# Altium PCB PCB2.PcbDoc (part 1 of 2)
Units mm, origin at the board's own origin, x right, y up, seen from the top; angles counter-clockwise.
Board outline 153.67 x 113.03 mm, 4 copper layers (Top Layer, Mid Layer 1, Mid Layer 2, Bottom Layer), stack 1.57 mm thick; 123 components, 293 nets, 917 pads, 135 vias.
Unrouted connection lines stored in the file: 517.
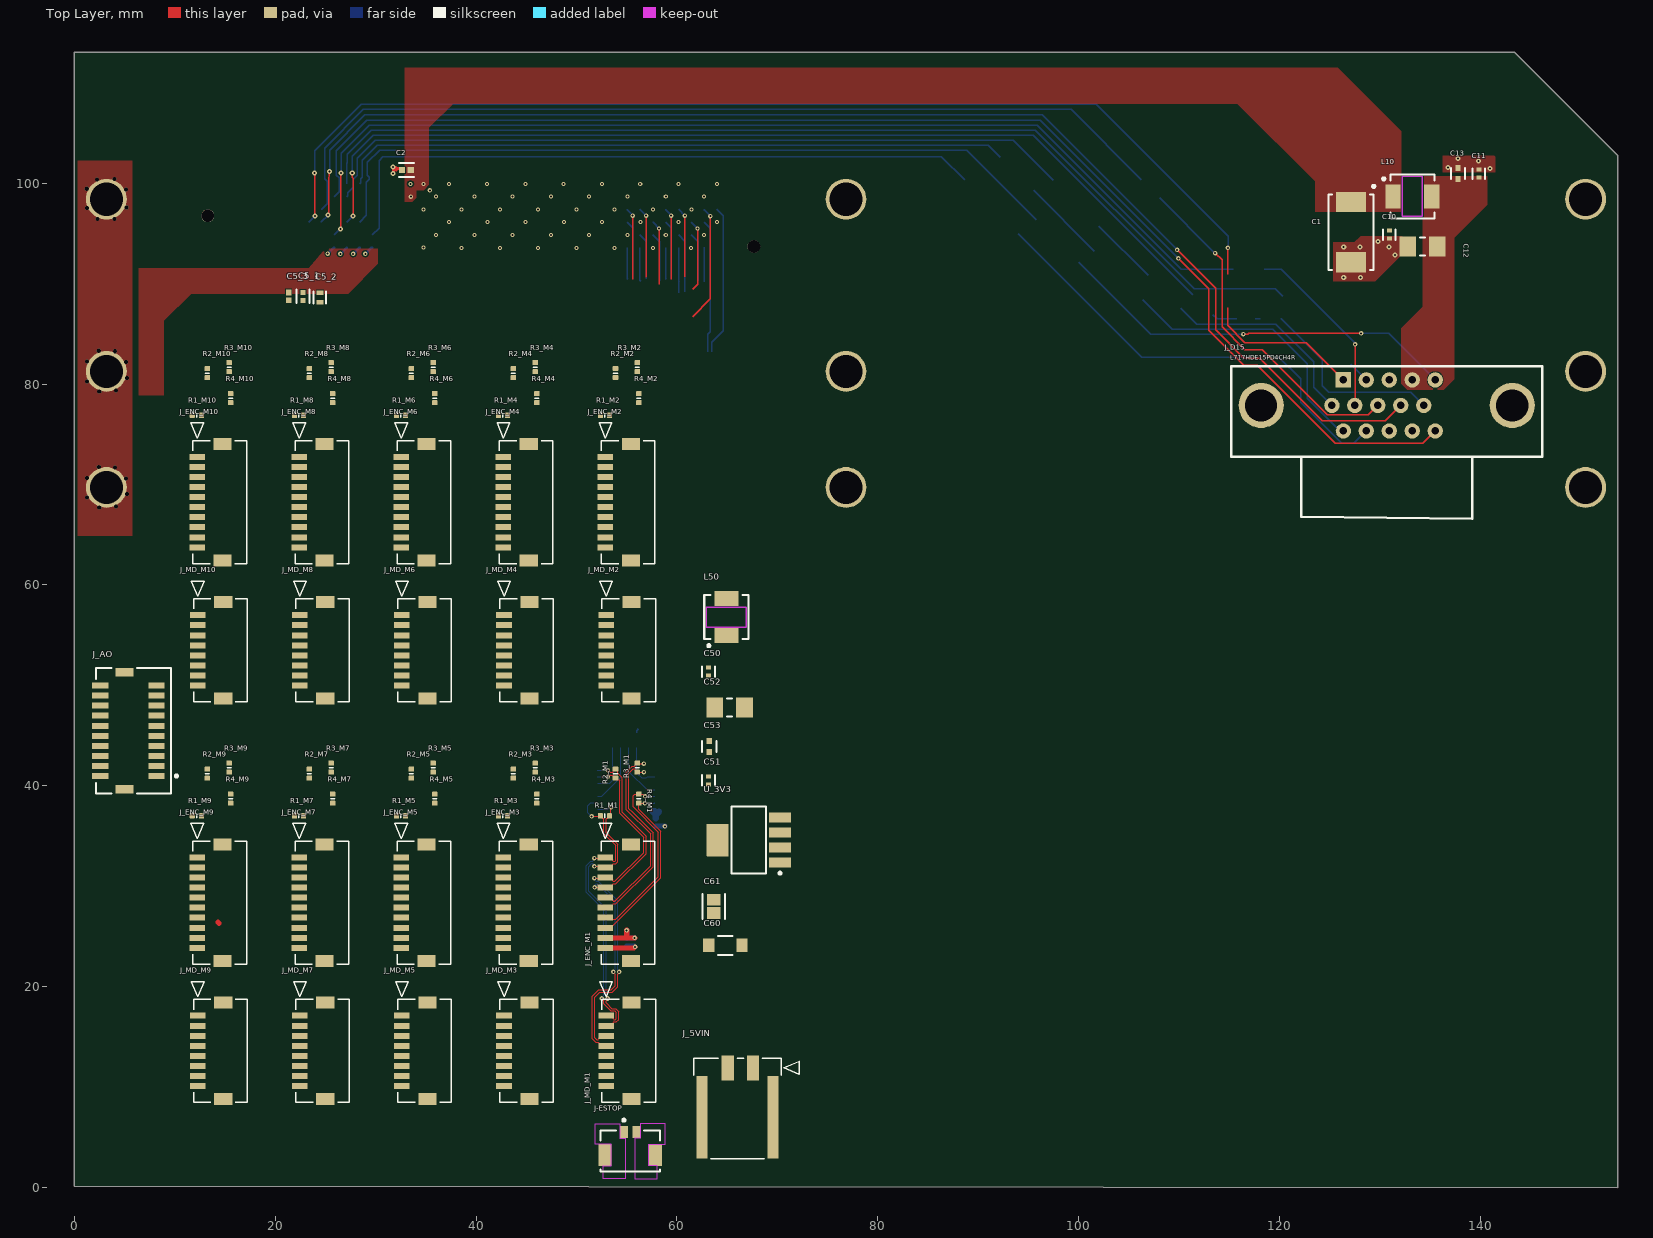
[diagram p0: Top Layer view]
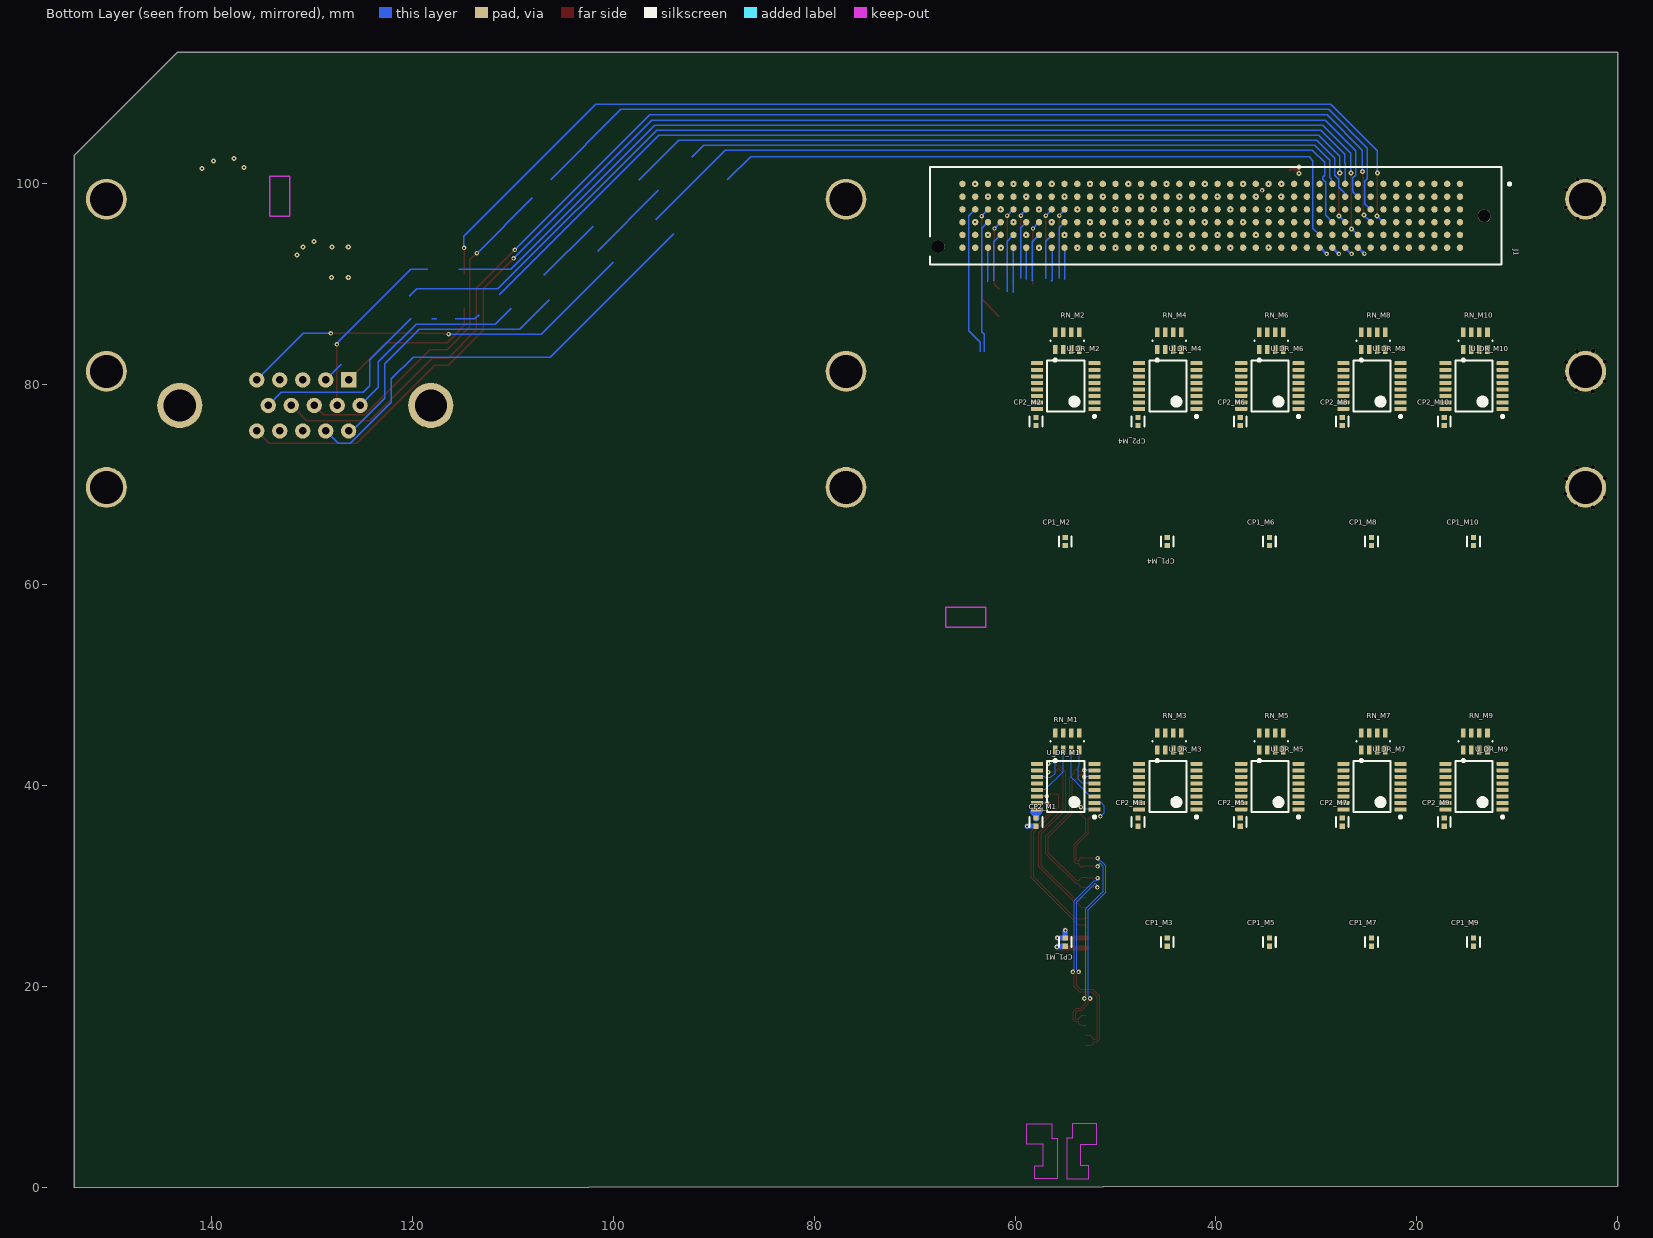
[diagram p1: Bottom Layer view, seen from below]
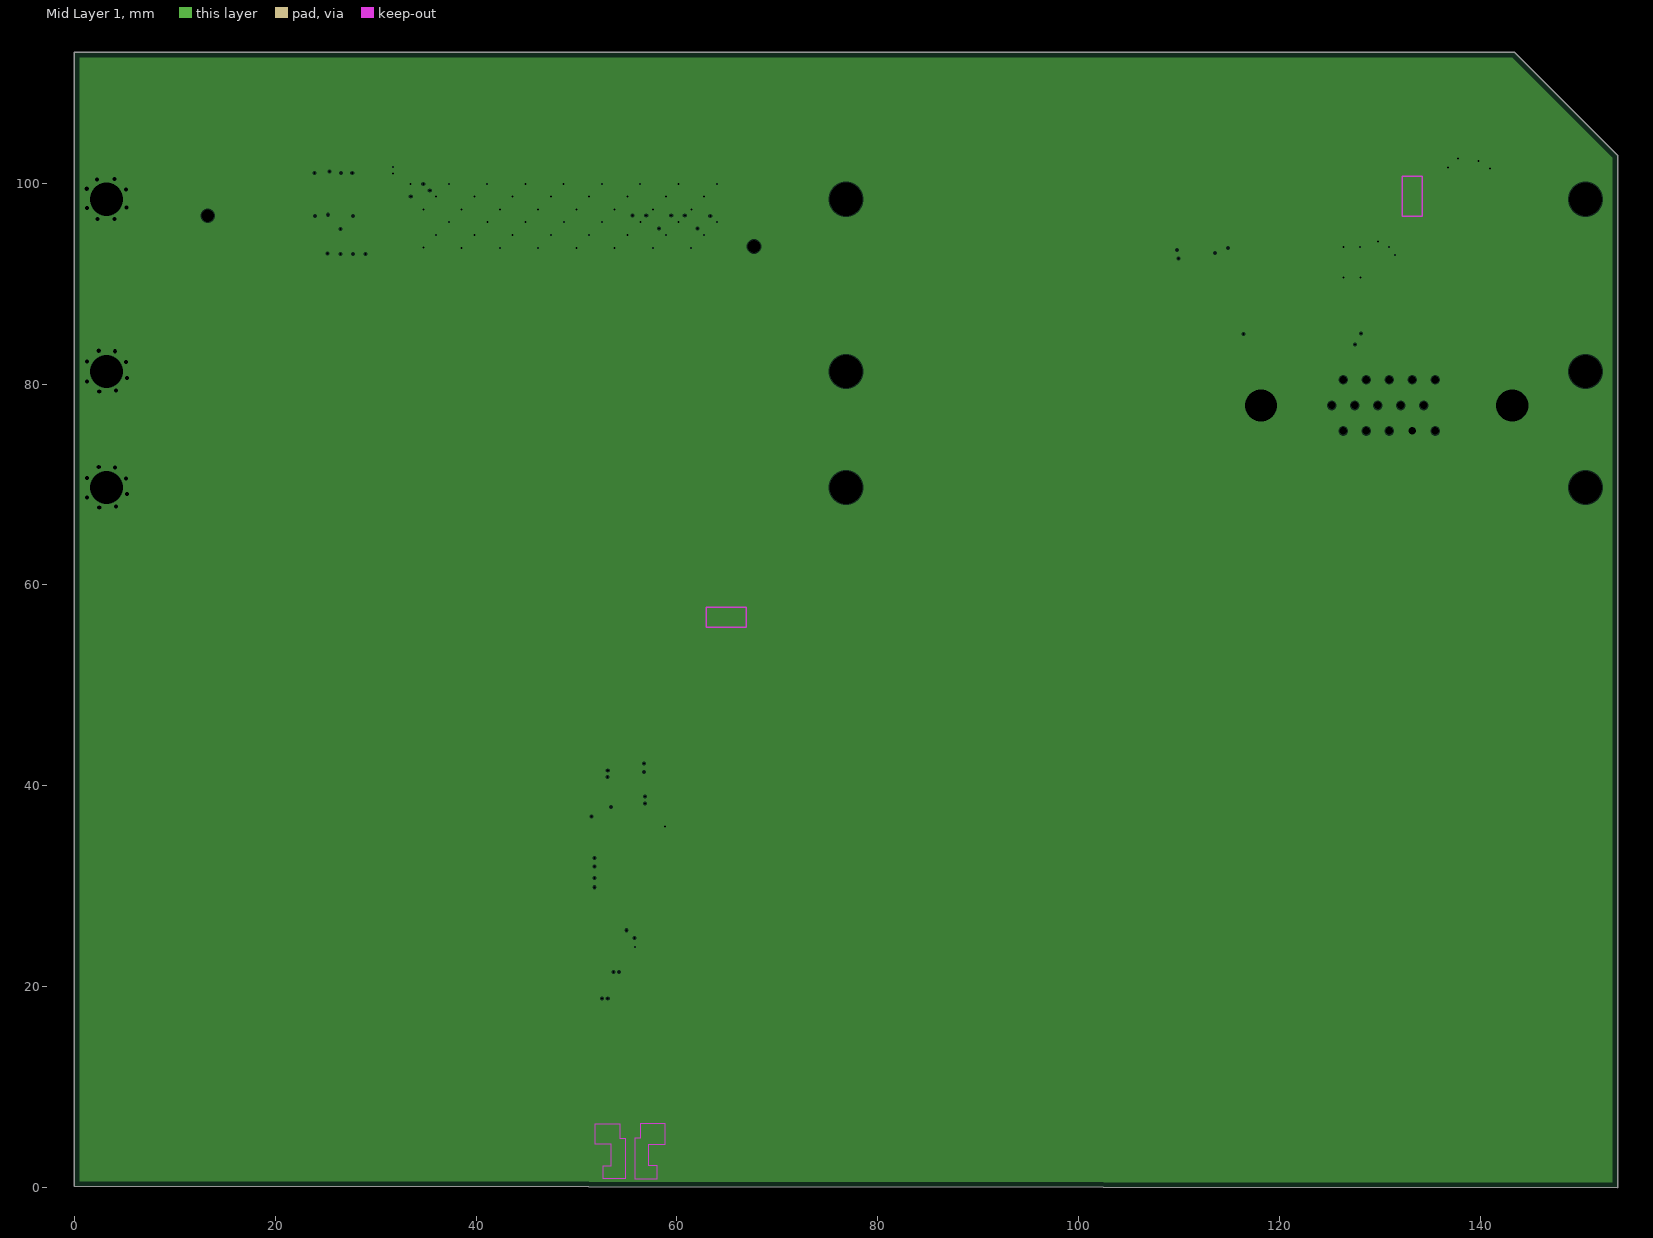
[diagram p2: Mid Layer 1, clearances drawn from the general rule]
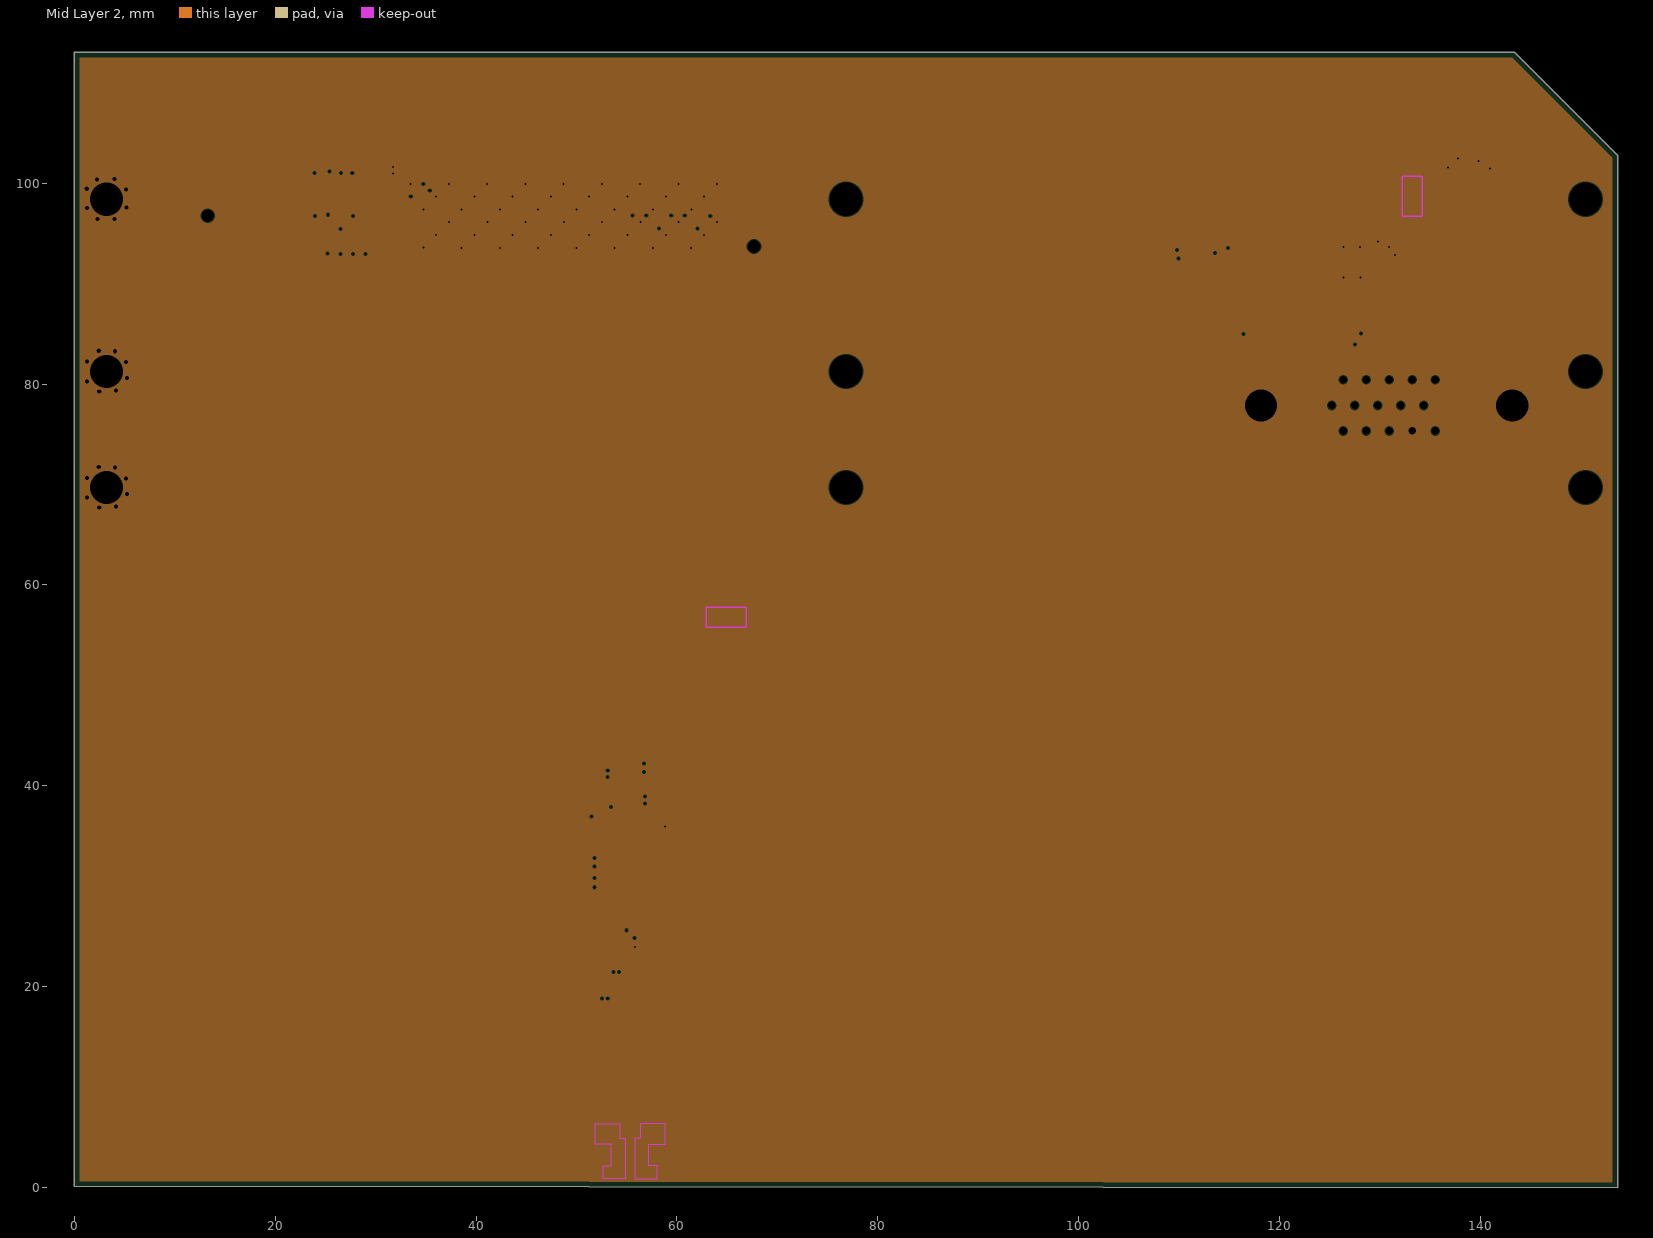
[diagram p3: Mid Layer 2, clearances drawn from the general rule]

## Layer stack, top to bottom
Top Solder: solder mask 0.0127, Solder Resist, Dk 3.8
Top Layer: signal copper 0.035
Dielectric 1: prepreg 0.1, 2313, Dk 4.05
Mid Layer 1: plane copper 0.0175, net GND
Core: core 1.265, FR-4, Dk 4.5
Mid Layer 2: plane copper 0.0175, net GND
Dielectric 2: prepreg 0.1, 2313, Dk 4.05
Bottom Layer: signal copper 0.035
Bottom Solder: solder mask 0.0127, Solder Resist, Dk 3.8

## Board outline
0,0.127 0,113.03 143.383,113.03 153.67,102.743 153.67,0

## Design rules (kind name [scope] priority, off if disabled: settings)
BoardOutlineClearance [All] p1: gap=0.2 ignorepadtopadclearanceinfootprint=FALSE
Clearance Clearance_diff-all [InAnyDifferentialPair vs NOT InAnyDifferentialPair] p1: gap=0.102 ignorepadtopadclearanceinfootprint=FALSE except(0.127: SMDPad-Via THPad-Via Via-Via Via-Fill Via-Poly Via-Region Via-Text; 0.25: Arc-Hole Track-Hole SMDPad-Hole THPad-Hole Via-Hole Fill-Hole Poly-Hole Region-Hole Text-Hole; 0.305: Arc-Arc Arc-Track Arc-SMDPad Arc-THPad Arc-Via Arc-Fill Arc-Poly Arc-Region Arc-Text Track-Track Track-SMDPad Track-THPad Track-Via Track-Fill Track-Poly Track-Region Track-Text)
Clearance Clearance_diff [InAnyDifferentialPair] p2: gap=0.102 ignorepadtopadclearanceinfootprint=FALSE except(0.127: SMDPad-Via THPad-Via Via-Via Via-Fill Via-Poly Via-Region Via-Text; 0.25: Arc-Hole Track-Hole SMDPad-Hole THPad-Hole Via-Hole Fill-Hole Poly-Hole Region-Hole Text-Hole; 0.305: Arc-Arc Arc-Track Arc-SMDPad Arc-THPad Arc-Via Arc-Fill Arc-Poly Arc-Region Track-Track Track-SMDPad Track-THPad Track-Via Track-Fill Track-Poly Track-Region)
Clearance Clr-cMdl-3H [(InNet('cMdlConn_1.CVRT_DIO3') OR InNet('cMdlConn_1.DONE#_DIO2') OR InNet('cMdlConn_1.ID_SELECT#') OR InNet('cMdlConn_1.MISO_DIO6') OR InNet('cMdlConn_1.MOSI_DIO7') OR InNet('cMdlConn_1.SLEEP') OR InNet('cMdlConn_1.SPICS#_DIO5') OR InNet('cMdlConn_1.SPIFUNC_DIO4') OR InNet('cMdlConn_1.SPI_CLK') OR InNet('cMdlConn_1.TRIG_DIO1') OR InNet('cMdlConn_1.OSCLK_DIO0'))] p3: gap=0.102 ignorepadtopadclearanceinfootprint=FALSE except(0.127: Arc-Via Track-Via SMDPad-Via THPad-Via Via-Via Via-Fill Via-Poly Via-Region Via-Text; 0.25: Arc-Hole Track-Hole SMDPad-Hole THPad-Hole Via-Hole Fill-Hole Poly-Hole Region-Hole Text-Hole; 0.361: Arc-Arc Arc-Track Track-Track)
Clearance Clr-DIO-2H [InNet('DIO*') OR InNetClass('MA[1..10]') OR InNetClass('SLO[1..10]') OR InNetClass('B[1..10]') OR InNetClass('A[1..10]') vs InNet('DIO*') OR InNetClass('MA[1..10]') OR InNetClass('SLO[1..10]') OR InNetClass('B[1..10]') OR InNetClass('A[1..10]')] p4: gap=0.102 ignorepadtopadclearanceinfootprint=FALSE except(0.127: Arc-Via Track-Via SMDPad-Via THPad-Via Via-Via Via-Fill Via-Poly Via-Region Via-Text; 0.241: Arc-Arc Arc-Track Track-Track; 0.25: Arc-Hole Track-Hole SMDPad-Hole THPad-Hole Via-Hole Fill-Hole Poly-Hole Region-Hole Text-Hole)
Clearance [All] p5: gap=0.102 ignorepadtopadclearanceinfootprint=FALSE except(0.127: Arc-Via Track-Via SMDPad-Via THPad-Via Via-Via Via-Fill Via-Poly Via-Region Via-Text; 0.25: Arc-Hole Track-Hole SMDPad-Hole THPad-Hole Via-Hole Fill-Hole Poly-Hole Region-Hole Text-Hole)
ComponentClearance [All] p1: gap=0.102 collisioncheckmode=3 verticalgap=0.102 showdistances=TRUE
DiffPairsRouting [InDifferentialPairClass('All Differential Pairs')] p1: maxlimit=0.127 minlimit=0.127 mostfreqgap=0.127 toplayer_minwidth=0.114 toplayer_maxwidth=0.114 toplayer_prefwidth=0.114 bottomlayer_minwidth=0.114 bottomlayer_maxwidth=0.114 bottomlayer_prefwidth=0.114 impedanceprofiledriven=TRUE impedanceprofileid={108E68F5-FF74-4348-BC96-26AF44CCABF0} impedanceprofilevalue=100.000000 maxuncoupledlength=12.7
Height [All] p1: minheight=0 maxheight=1816.048 prefheight=12.7
HoleSize [All] p1: absolutevalues=TRUE maxlimit=6.3 minlimit=0.2 maxpercent=80.000 minpercent=20.000
HoleToHoleClearance [All] p1: gap=0.25 allowstackedmicrovias=FALSE
MinimumAnnularRing [All] p1: minimumring=0.076
MinimumSolderMaskSliver [All] p1: minsoldermaskwidth=0
PlaneClearance [All] p1: clearance=0.102
PlaneConnect PlaneConnectPowerPads [InPadClass('PowerPads')] p1: planeconnectstyle=Direct reliefexpansion=0.508 reliefentries=4 reliefconductorwidth=0.254 reliefairgap=0.254
PlaneConnect [All] p2: pad.planeconnectstyle=Relief pad.reliefexpansion=0.3 pad.reliefentries=4 pad.reliefconductorwidth=0.102 pad.reliefairgap=0.102 via.planeconnectstyle=Direct via.reliefexpansion=0.3 via.reliefentries=4 via.reliefconductorwidth=0.127 via.reliefairgap=0.127
PolygonConnect PolygonConnect_1 [InNamedPolygon('GND_L01_P000All')] p1: thpad.connectstyle=Direct thpad.reliefconductorwidth=0.254 thpad.reliefentries=4 thpad.polygonreliefangle="90 Angle" thpad.airgapwidth=0.254 smdpad.connectstyle=Relief smdpad.reliefconductorwidth=0.254 smdpad.reliefentries=4 smdpad.polygonreliefangle="90 Angle" smdpad.airgapwidth=0.254 via.connectstyle=Relief via.reliefconductorwidth=0.254 via.reliefentries=4 via.polygonreliefangle="90 Angle" via.airgapwidth=0.254
PolygonConnect PolygonConnectPowerPads [All] p2: connectstyle=Direct reliefconductorwidth=0.254 reliefentries=4 polygonreliefangle="90 Angle" airgapwidth=0.254
PolygonConnect [HasFootprint('No Footprint') And OnLayer('Top Layer')] p3: thpad.connectstyle=Relief thpad.reliefconductorwidth=0.102 thpad.reliefentries=4 thpad.polygonreliefangle="90 Angle" thpad.airgapwidth=0.102 smdpad.connectstyle=Relief smdpad.reliefconductorwidth=0.102 smdpad.reliefentries=4 smdpad.polygonreliefangle="90 Angle" smdpad.airgapwidth=0.102 via.connectstyle=Direct via.reliefconductorwidth=0.127 via.reliefentries=4 via.polygonreliefangle="90 Angle" via.airgapwidth=0.127
RoutingVias [All] p1: holewidth=0.2 width=0.45 viastyle="Through Hole" minholewidth=0.2 minwidth=0.45 maxholewidth=6.3 maxwidth=6.55
SilkToSilkClearance [All] p1: silktosilkclearance=0
SilkToSolderMaskClearance [IsPad] p1: minsilkscreentomaskgap=0.102 clearancetoexposedcopper=TRUE
SolderMaskExpansion [All] p1: expansion=0.075 istentingtop=FALSE
Width Width_cMdl [(InNet('cMdlConn_1.CVRT_DIO3') OR InNet('cMdlConn_1.DONE#_DIO2') OR InNet('cMdlConn_1.ID_SELECT#') OR InNet('cMdlConn_1.MISO_DIO6') OR InNet('cMdlConn_1.MOSI_DIO7') OR InNet('cMdlConn_1.SLEEP') OR InNet('cMdlConn_1.SPICS#_DIO5') OR InNet('cMdlConn_1.SPIFUNC_DIO4') OR InNet('cMdlConn_1.SPI_CLK') OR InNet('cMdlConn_1.TRIG_DIO1') OR InNet('cMdlConn_1.OSCLK_DIO0'))] p1: maxlimit=0.142 minlimit=0.142 preferedwidth=0.142 impedanceprofiledriven=TRUE impedanceprofileid={8E04676D-BDB6-42E6-A15F-76CBDF29C3C9} impedanceprofilevalue=55.000000 minimp=50.000000 maximp=50.000000 favimp=50.000000
Width Width_DIO [InNetClass('DIO[0..95]')] p2: maxlimit=0.142 minlimit=0.142 preferedwidth=0.142 impedanceprofiledriven=TRUE impedanceprofileid={8E04676D-BDB6-42E6-A15F-76CBDF29C3C9} impedanceprofilevalue=55.000000 minimp=50.000000 maximp=50.000000 favimp=50.000000
Width [All] p3: maxlimit=1816.048 minlimit=0.102 preferedwidth=0.102
20 further rules are at their usual default settings.

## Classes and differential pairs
net class SLO[1..10]: DIO0 DIO1 DIO2 DIO3 DIO4 DIO5 DIO6 DIO7 DIO8 DIO9
net class MA[1..10]: DIO32 DIO33 DIO34 DIO35 DIO36 DIO37 DIO38 DIO39 DIO40 DIO41
net class DIO[0..95]: A1 A2 A3 A4 A5 A6 A7 A8 A9 A10 B1 B2 B3 B4 B5 B6 B7 B8 B9 B10 DIO0 DIO1 DIO2 DIO3 DIO4 DIO5 DIO6 DIO7 DIO8 DIO9 DIO10 DIO11 DIO12 DIO13 DIO14 DIO15 DIO26 DIO27 DIO28 DIO29 DIO30 DIO31 DIO32 DIO33 DIO34 DIO35 DIO36 DIO37 DIO38 DIO39 DIO40 DIO41 DIO42 DIO43 DIO44 DIO45 DIO46 DIO47 DIO48 DIO49 DIO50 DIO51 DIO52 DIO53 DIO54 DIO55 DIO56 DIO57 DIO58 DIO59 DIO60 DIO61 DIO62 DIO63 DIO74 DIO75 DIO76 DIO77 DIO78 DIO79 DIO80 DIO81 DIO82 DIO83 DIO84 DIO85 DIO86 DIO87 DIO88 DIO89 DIO90 DIO91 DIO92 DIO93 DIO94 DIO95
net class B[1..10]: B1 B2 B3 B4 B5 B6 B7 B8 B9 B10
channel class Enc-Driver-Junction: M1 M2 M3 M4 M5 M6 M7 M8 M9 M10
net class ANA[1..10]: ANA1 ANA2 ANA3 ANA4 ANA5 ANA6 ANA7 ANA8 ANA9 ANA10
net class A[1..10]: A1 A2 A3 A4 A5 A6 A7 A8 A9 A10
component class TopLevel: C50 C51 C52 C53 C60 C61 J-ESTOP J_5VIN L50 U_3V3
component class M10: CP1_M10 CP2_M10 J_ENC_M10 J_MD_M10 R1_M10 R2_M10 R3_M10 R4_M10 RN_M10 U_DR_M10
component class M9: CP1_M9 CP2_M9 J_ENC_M9 J_MD_M9 R1_M9 R2_M9 R3_M9 R4_M9 RN_M9 U_DR_M9
component class M8: CP1_M8 CP2_M8 J_ENC_M8 J_MD_M8 R1_M8 R2_M8 R3_M8 R4_M8 RN_M8 U_DR_M8
component class M7: CP1_M7 CP2_M7 J_ENC_M7 J_MD_M7 R1_M7 R2_M7 R3_M7 R4_M7 RN_M7 U_DR_M7
component class M6: CP1_M6 CP2_M6 J_ENC_M6 J_MD_M6 R1_M6 R2_M6 R3_M6 R4_M6 RN_M6 U_DR_M6
component class M5: CP1_M5 CP2_M5 J_ENC_M5 J_MD_M5 R1_M5 R2_M5 R3_M5 R4_M5 RN_M5 U_DR_M5
component class M4: CP1_M4 CP2_M4 J_ENC_M4 J_MD_M4 R1_M4 R2_M4 R3_M4 R4_M4 RN_M4 U_DR_M4
component class M3: CP1_M3 CP2_M3 J_ENC_M3 J_MD_M3 R1_M3 R2_M3 R3_M3 R4_M3 RN_M3 U_DR_M3
component class M2: CP1_M2 CP2_M2 J_ENC_M2 J_MD_M2 R1_M2 R2_M2 R3_M2 R4_M2 RN_M2 U_DR_M2
component class M1: CP1_M1 CP2_M1 J_ENC_M1 J_MD_M1 R1_M1 R2_M1 R3_M1 R4_M1 RN_M1 U_DR_M1
component class "RMC Conn.": C5_1 C5_2 C5_3 J1
component class cMdl_1: C1 C2 C10 C11 C12 C13 J_AO J_D15 L10
differential pair SLO_M10: +SLO_M10_P -SLO_M10_N
differential pair SLO_M9: +SLO_M9_P -SLO_M9_N
differential pair SLO_M8: +SLO_M8_P -SLO_M8_N
differential pair SLO_M7: +SLO_M7_P -SLO_M7_N
differential pair SLO_M6: +SLO_M6_P -SLO_M6_N
differential pair SLO_M5: +SLO_M5_P -SLO_M5_N
differential pair SLO_M4: +SLO_M4_P -SLO_M4_N
differential pair SLO_M3: +SLO_M3_P -SLO_M3_N
differential pair SLO_M2: +SLO_M2_P -SLO_M2_N
differential pair SLO_M1: +SLO_M1_P -SLO_M1_N
differential pair MA_M10: +MA_M10_P -MA_M10_N
differential pair MA_M9: +MA_M9_P -MA_M9_N
differential pair MA_M8: +MA_M8_P -MA_M8_N
differential pair MA_M7: +MA_M7_P -MA_M7_N
differential pair MA_M6: +MA_M6_P -MA_M6_N
differential pair MA_M5: +MA_M5_P -MA_M5_N
differential pair MA_M4: +MA_M4_P -MA_M4_N
differential pair MA_M3: +MA_M3_P -MA_M3_N
differential pair MA_M2: +MA_M2_P -MA_M2_N
differential pair MA_M1: +MA_M1_P -MA_M1_N
differential pair B_M10: +B_M10_P -B_M10_N
differential pair B_M9: +B_M9_P -B_M9_N
differential pair B_M8: +B_M8_P -B_M8_N
differential pair B_M7: +B_M7_P -B_M7_N
differential pair B_M6: +B_M6_P -B_M6_N
differential pair B_M5: +B_M5_P -B_M5_N
differential pair B_M4: +B_M4_P -B_M4_N
differential pair B_M3: +B_M3_P -B_M3_N
differential pair B_M2: +B_M2_P -B_M2_N
differential pair B_M1: +B_M1_P -B_M1_N
differential pair A_M10: +A_M10_P -A_M10_N
differential pair A_M9: +A_M9_P -A_M9_N
differential pair A_M8: +A_M8_P -A_M8_N
differential pair A_M7: +A_M7_P -A_M7_N
differential pair A_M6: +A_M6_P -A_M6_N
differential pair A_M5: +A_M5_P -A_M5_N
differential pair A_M4: +A_M4_P -A_M4_N
differential pair A_M3: +A_M3_P -A_M3_N
differential pair A_M2: +A_M2_P -A_M2_N
differential pair A_M1: +A_M1_P -A_M1_N

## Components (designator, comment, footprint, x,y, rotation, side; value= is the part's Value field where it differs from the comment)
C1 "TPSD337K006R0050" CAPMP7344X31-T_V 127.127,95.123 r270 top
C2 "GRM155R60J475ME47D" FP-GRM155-0_1-IPC_B 33.071,101.295 r180 top
C5_1 "C0402C105K8PACTU" FP-C0402C105K8PACTU-MFG 22.784,88.722 r270 top
C5_2 "CL05A106MP5NUNC" FP-CL05A106MP5NUNC-MFG 24.46,88.626 r270 top value=10uF
C5_3 "04026D104KAT2A" CAPC1005X56X25LL10T15 21.336,88.731 r90 top
C10 "GRM155R71C104KA88D" FP-GRM15-MFG 130.937,94.869 r90 top value=0.10μF
C11 "GRM155R71C104KA88D" FP-GRM15-MFG 139.852,100.94 r270 top value=0.10μF
C12 "GRM31CR60J107ME39L" CAPC3216X190X55ML30T25 134.237,93.701 r0 top
C13 "0402YC103KAT2A" FP-0402-L_1_0_1-W_0_5_0_1-MFG 137.77,100.965 r90 top
C50 "GRM155R71C104KA88D" FP-GRM15-MFG 63.144,51.359 r90 top value=0.10μF
C51 "GRM155R71C104KA88D" FP-GRM15-MFG 63.144,40.538 r90 top value=0.10μF
C52 "GRM31CR60J107ME39L" CAPC3216X190X55ML30T25 65.253,47.777 r180 top
C53 "0402YC103KAT2A" FP-0402-L_1_0_1-W_0_5_0_1-MFG 63.221,43.917 r90 top
C60 "C3216X5R1A686M160AC" FP-C3216-160-0_3-MFG 64.821,24.105 r180 top
C61 "C2012X5R0J336M125AC" FP-C2012-125-0_2-IPC_C 63.652,27.991 r90 top
CP1_M1 "C0402C104K8PACTU" FP-C0402-BB-MFG 55.004,24.435 r270 bottom value="0.10 μF" (schematic designator CP1)
CP1_M2 "C0402C104K8PACTU" FP-C0402-BB-MFG 55.004,64.313 r270 bottom value="0.10 μF" (schematic designator CP1)
CP1_M3 "C0402C104K8PACTU" FP-C0402-BB-MFG 44.844,24.435 r270 bottom value="0.10 μF" (schematic designator CP1)
CP1_M4 "C0402C104K8PACTU" FP-C0402-BB-MFG 44.844,64.313 r270 bottom value="0.10 μF" (schematic designator CP1)
CP1_M5 "C0402C104K8PACTU" FP-C0402-BB-MFG 34.684,24.435 r270 bottom value="0.10 μF" (schematic designator CP1)
CP1_M6 "C0402C104K8PACTU" FP-C0402-BB-MFG 34.684,64.313 r270 bottom value="0.10 μF" (schematic designator CP1)
CP1_M7 "C0402C104K8PACTU" FP-C0402-BB-MFG 24.524,24.435 r270 bottom value="0.10 μF" (schematic designator CP1)
CP1_M8 "C0402C104K8PACTU" FP-C0402-BB-MFG 24.524,64.313 r270 bottom value="0.10 μF" (schematic designator CP1)
CP1_M9 "C0402C104K8PACTU" FP-C0402-BB-MFG 14.364,24.435 r270 bottom value="0.10 μF" (schematic designator CP1)
CP1_M10 "C0402C104K8PACTU" FP-C0402-BB-MFG 14.364,64.313 r270 bottom value="0.10 μF" (schematic designator CP1)
CP2_M1 "C0402C104K8PACTU" FP-C0402-BB-MFG 57.912,36.379 r270 bottom value="0.10 μF" (schematic designator CP2)
CP2_M2 "C0402C104K8PACTU" FP-C0402-BB-MFG 57.912,76.257 r270 bottom value="0.10 μF" (schematic designator CP2)
CP2_M3 "C0402C104K8PACTU" FP-C0402-BB-MFG 47.752,36.379 r270 bottom value="0.10 μF" (schematic designator CP2)
CP2_M4 "C0402C104K8PACTU" FP-C0402-BB-MFG 47.752,76.257 r270 bottom value="0.10 μF" (schematic designator CP2)
CP2_M5 "C0402C104K8PACTU" FP-C0402-BB-MFG 37.592,36.379 r270 bottom value="0.10 μF" (schematic designator CP2)
CP2_M6 "C0402C104K8PACTU" FP-C0402-BB-MFG 37.592,76.257 r270 bottom value="0.10 μF" (schematic designator CP2)
CP2_M7 "C0402C104K8PACTU" FP-C0402-BB-MFG 27.432,36.379 r270 bottom value="0.10 μF" (schematic designator CP2)
CP2_M8 "C0402C104K8PACTU" FP-C0402-BB-MFG 27.432,76.257 r270 bottom value="0.10 μF" (schematic designator CP2)
CP2_M9 "C0402C104K8PACTU" FP-C0402-BB-MFG 17.272,36.379 r270 bottom value="0.10 μF" (schematic designator CP2)
CP2_M10 "C0402C104K8PACTU" FP-C0402-BB-MFG 17.272,76.257 r270 bottom value="0.10 μF" (schematic designator CP2)
J1 "SEAM-40-03.0-S-06-2-A-K-TR" FP-SEAM-40-03_0-S-06-2-A-MFG 40.03,96.749 r180 bottom locked
J-ESTOP "5055670271" FP-5055670271-MFG 55.347,3.632 r180 top
J_5VIN "1054301102" CON_1054301102_MOL 67.575,11.915 r0 top
J_AO "501190-2017" FP-501190-2017-MFG 5.391,45.474 r90 top
J_D15 "D-SUB High Density 15 Position Male Conn" "D-SUB High Density 15 Position Male Conn-Footprint-1" 130.67,77.87 r0 top locked
J_ENC_M1 "5013311007" PicoClasp_Rcpt_10Pos_Vert 52.885,32.863 r90 top (schematic designator J_ENC)
J_ENC_M2 "5013311007" PicoClasp_Rcpt_10Pos_Vert 52.885,72.741 r90 top (schematic designator J_ENC)
J_ENC_M3 "5013311007" PicoClasp_Rcpt_10Pos_Vert 42.725,32.863 r90 top (schematic designator J_ENC)
J_ENC_M4 "5013311007" PicoClasp_Rcpt_10Pos_Vert 42.725,72.741 r90 top (schematic designator J_ENC)
J_ENC_M5 "5013311007" PicoClasp_Rcpt_10Pos_Vert 32.565,32.863 r90 top (schematic designator J_ENC)
J_ENC_M6 "5013311007" PicoClasp_Rcpt_10Pos_Vert 32.565,72.741 r90 top (schematic designator J_ENC)
J_ENC_M7 "5013311007" PicoClasp_Rcpt_10Pos_Vert 22.405,32.863 r90 top (schematic designator J_ENC)
J_ENC_M8 "5013311007" PicoClasp_Rcpt_10Pos_Vert 22.405,72.741 r90 top (schematic designator J_ENC)
J_ENC_M9 "5013311007" PicoClasp_Rcpt_10Pos_Vert 12.245,32.863 r90 top (schematic designator J_ENC)
J_ENC_M10 "5013311007" PicoClasp_Rcpt_10Pos_Vert 12.245,72.741 r90 top (schematic designator J_ENC)
J_MD_M1 "5013310807" CON_5013310807 52.946,17.106 r90 top (schematic designator J_MD)
J_MD_M2 "5013310807" CON_5013310807 52.946,56.984 r90 top (schematic designator J_MD)
J_MD_M3 "5013310807" CON_5013310807 42.786,17.106 r90 top (schematic designator J_MD)
J_MD_M4 "5013310807" CON_5013310807 42.786,56.984 r90 top (schematic designator J_MD)
J_MD_M5 "5013310807" CON_5013310807 32.626,17.106 r90 top (schematic designator J_MD)
J_MD_M6 "5013310807" CON_5013310807 32.626,56.984 r90 top (schematic designator J_MD)
J_MD_M7 "5013310807" CON_5013310807 22.466,17.106 r90 top (schematic designator J_MD)
J_MD_M8 "5013310807" CON_5013310807 22.466,56.984 r90 top (schematic designator J_MD)
J_MD_M9 "5013310807" CON_5013310807 12.306,17.106 r90 top (schematic designator J_MD)
J_MD_M10 "5013310807" CON_5013310807 12.306,56.984 r90 top (schematic designator J_MD)
L10 "74437324068" "WE-LHMI 4020"#1 133.223,98.679 r0 top
L50 "74437324068" "WE-LHMI 4020"#2 64.922,56.794 r90 top
R1_M1 "Resistor 100R +/-1 % 0402 63 mW" RESC0402(1005)_L 52.838,36.999 r0 top value=100 (schematic designator R1)
R1_M2 "Resistor 100R +/-1 % 0402 63 mW" RESC0402(1005)_L 52.838,76.877 r0 top value=100 (schematic designator R1)
R1_M3 "Resistor 100R +/-1 % 0402 63 mW" RESC0402(1005)_L 42.678,36.999 r0 top value=100 (schematic designator R1)
R1_M4 "Resistor 100R +/-1 % 0402 63 mW" RESC0402(1005)_L 42.678,76.877 r0 top value=100 (schematic designator R1)
R1_M5 "Resistor 100R +/-1 % 0402 63 mW" RESC0402(1005)_L 32.518,36.999 r0 top value=100 (schematic designator R1)
R1_M6 "Resistor 100R +/-1 % 0402 63 mW" RESC0402(1005)_L 32.518,76.877 r0 top value=100 (schematic designator R1)
R1_M7 "Resistor 100R +/-1 % 0402 63 mW" RESC0402(1005)_L 22.358,36.999 r0 top value=100 (schematic designator R1)
R1_M8 "Resistor 100R +/-1 % 0402 63 mW" RESC0402(1005)_L 22.358,76.877 r0 top value=100 (schematic designator R1)
R1_M9 "Resistor 100R +/-1 % 0402 63 mW" RESC0402(1005)_L 12.198,36.999 r0 top value=100 (schematic designator R1)
R1_M10 "Resistor 100R +/-1 % 0402 63 mW" RESC0402(1005)_L 12.198,76.877 r0 top value=100 (schematic designator R1)
R2_M1 "Resistor 100R +/-1 % 0402 63 mW" RESC0402(1005)_L 53.886,41.204 r90 top value=100 (schematic designator R2)
R2_M2 "Resistor 100R +/-1 % 0402 63 mW" RESC0402(1005)_L 53.886,81.082 r90 top value=100 (schematic designator R2)
R2_M3 "Resistor 100R +/-1 % 0402 63 mW" RESC0402(1005)_L 43.726,41.204 r90 top value=100 (schematic designator R2)
R2_M4 "Resistor 100R +/-1 % 0402 63 mW" RESC0402(1005)_L 43.726,81.082 r90 top value=100 (schematic designator R2)
R2_M5 "Resistor 100R +/-1 % 0402 63 mW" RESC0402(1005)_L 33.566,41.204 r90 top value=100 (schematic designator R2)
R2_M6 "Resistor 100R +/-1 % 0402 63 mW" RESC0402(1005)_L 33.566,81.082 r90 top value=100 (schematic designator R2)
R2_M7 "Resistor 100R +/-1 % 0402 63 mW" RESC0402(1005)_L 23.406,41.204 r90 top value=100 (schematic designator R2)
R2_M8 "Resistor 100R +/-1 % 0402 63 mW" RESC0402(1005)_L 23.406,81.082 r90 top value=100 (schematic designator R2)
R2_M9 "Resistor 100R +/-1 % 0402 63 mW" RESC0402(1005)_L 13.246,41.204 r90 top value=100 (schematic designator R2)
R2_M10 "Resistor 100R +/-1 % 0402 63 mW" RESC0402(1005)_L 13.246,81.082 r90 top value=100 (schematic designator R2)
R3_M1 "Resistor 100R +/-1 % 0402 63 mW" RESC0402(1005)_L 56.058,41.801 r270 top value=100 (schematic designator R3)
R3_M2 "Resistor 100R +/-1 % 0402 63 mW" RESC0402(1005)_L 56.058,81.679 r270 top value=100 (schematic designator R3)
R3_M3 "Resistor 100R +/-1 % 0402 63 mW" RESC0402(1005)_L 45.898,41.801 r270 top value=100 (schematic designator R3)
R3_M4 "Resistor 100R +/-1 % 0402 63 mW" RESC0402(1005)_L 45.898,81.679 r270 top value=100 (schematic designator R3)
R3_M5 "Resistor 100R +/-1 % 0402 63 mW" RESC0402(1005)_L 35.738,41.801 r270 top value=100 (schematic designator R3)
R3_M6 "Resistor 100R +/-1 % 0402 63 mW" RESC0402(1005)_L 35.738,81.679 r270 top value=100 (schematic designator R3)
R3_M7 "Resistor 100R +/-1 % 0402 63 mW" RESC0402(1005)_L 25.578,41.801 r270 top value=100 (schematic designator R3)
R3_M8 "Resistor 100R +/-1 % 0402 63 mW" RESC0402(1005)_L 25.578,81.679 r270 top value=100 (schematic designator R3)
R3_M9 "Resistor 100R +/-1 % 0402 63 mW" RESC0402(1005)_L 15.418,41.801 r270 top value=100 (schematic designator R3)
R3_M10 "Resistor 100R +/-1 % 0402 63 mW" RESC0402(1005)_L 15.418,81.679 r270 top value=100 (schematic designator R3)
R4_M1 "Resistor 100R +/-1 % 0402 63 mW" RESC0402(1005)_L 56.21,38.717 r270 top value=100 (schematic designator R4)
R4_M2 "Resistor 100R +/-1 % 0402 63 mW" RESC0402(1005)_L 56.21,78.595 r270 top value=100 (schematic designator R4)
R4_M3 "Resistor 100R +/-1 % 0402 63 mW" RESC0402(1005)_L 46.05,38.717 r270 top value=100 (schematic designator R4)
R4_M4 "Resistor 100R +/-1 % 0402 63 mW" RESC0402(1005)_L 46.05,78.595 r270 top value=100 (schematic designator R4)
R4_M5 "Resistor 100R +/-1 % 0402 63 mW" RESC0402(1005)_L 35.89,38.717 r270 top value=100 (schematic designator R4)
R4_M6 "Resistor 100R +/-1 % 0402 63 mW" RESC0402(1005)_L 35.89,78.595 r270 top value=100 (schematic designator R4)
R4_M7 "Resistor 100R +/-1 % 0402 63 mW" RESC0402(1005)_L 25.73,38.717 r270 top value=100 (schematic designator R4)
R4_M8 "Resistor 100R +/-1 % 0402 63 mW" RESC0402(1005)_L 25.73,78.595 r270 top value=100 (schematic designator R4)
R4_M9 "Resistor 100R +/-1 % 0402 63 mW" RESC0402(1005)_L 15.57,38.717 r270 top value=100 (schematic designator R4)
R4_M10 "Resistor 100R +/-1 % 0402 63 mW" RESC0402(1005)_L 15.57,78.595 r270 top value=100 (schematic designator R4)
RN_M1 "742C083470JP" FP-742C083-MFG 54.807,44.425 r180 bottom (schematic designator RN)
RN_M2 "742C083470JP" FP-742C083-MFG 54.807,84.303 r180 bottom (schematic designator RN)
RN_M3 "742C083470JP" FP-742C083-MFG 44.647,44.425 r180 bottom (schematic designator RN)
RN_M4 "742C083470JP" FP-742C083-MFG 44.647,84.303 r180 bottom (schematic designator RN)
RN_M5 "742C083470JP" FP-742C083-MFG 34.487,44.425 r180 bottom (schematic designator RN)
RN_M6 "742C083470JP" FP-742C083-MFG 34.487,84.303 r180 bottom (schematic designator RN)
RN_M7 "742C083470JP" FP-742C083-MFG 24.327,44.425 r180 bottom (schematic designator RN)
RN_M8 "742C083470JP" FP-742C083-MFG 24.327,84.303 r180 bottom (schematic designator RN)
RN_M9 "742C083470JP" FP-742C083-MFG 14.167,44.425 r180 bottom (schematic designator RN)
RN_M10 "742C083470JP" FP-742C083-MFG 14.167,84.303 r180 bottom (schematic designator RN)
U_3V3 "LP3962EMP-3.3/NOPB" NDC0005A_M 67.158,34.595 r180 top
U_DR_M1 "AM26LV32EIPWR" PW0016A_L 54.953,39.916 r0 bottom (schematic designator U_DR)
U_DR_M2 "AM26LV32EIPWR" PW0016A_L 54.953,79.794 r0 bottom (schematic designator U_DR)
U_DR_M3 "AM26LV32EIPWR" PW0016A_L 44.793,39.916 r0 bottom (schematic designator U_DR)
U_DR_M4 "AM26LV32EIPWR" PW0016A_L 44.793,79.794 r0 bottom (schematic designator U_DR)
U_DR_M5 "AM26LV32EIPWR" PW0016A_L 34.633,39.916 r0 bottom (schematic designator U_DR)
U_DR_M6 "AM26LV32EIPWR" PW0016A_L 34.633,79.794 r0 bottom (schematic designator U_DR)
U_DR_M7 "AM26LV32EIPWR" PW0016A_L 24.473,39.916 r0 bottom (schematic designator U_DR)
U_DR_M8 "AM26LV32EIPWR" PW0016A_L 24.473,79.794 r0 bottom (schematic designator U_DR)
U_DR_M9 "AM26LV32EIPWR" PW0016A_L 14.313,39.916 r0 bottom (schematic designator U_DR)
U_DR_M10 "AM26LV32EIPWR" PW0016A_L 14.313,79.794 r0 bottom (schematic designator U_DR)

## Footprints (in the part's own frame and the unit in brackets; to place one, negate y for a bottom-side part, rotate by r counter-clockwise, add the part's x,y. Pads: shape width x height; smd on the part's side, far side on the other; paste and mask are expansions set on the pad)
CAPC1005X56X25LL10T15 [mm] "Chip Capacitor, 2-Leads, Body 1.00x0.50mm, IPC High Density"
  rect 0.58x0.54 smd: 1(-0.39,0) 2(0.39,0)
  body extent -0.55,-0.3 0.55,0.3, height 0.56
CAPC3216X190X55ML30T25 [mm] "Chip Capacitor, 2-Leads, Body 3.5x1.9mm, IPC Low Density"
  rect 1.65x2 smd: 1(-1.475,0) 2(1.475,0)
  silkscreen extent -0.25,-0.9 0.25,0.9, body extent -1.75,-0.95 1.75,0.95, height 1.9
CAPMP7344X31-T_V [mm] "Molded Capacitor, 2-Leads, Body 7.50x4.5mm"
  rect 2x3 smd: 1(-3,0) 2(3,0)
  silkscreen extent -4.67,-2.25 3.75,2.38, body extent -3.97,-2.25 3.97,2.25, height 3.1
CON_1054301102_MOL [mm]
  rect 1.24x2.5 smd paste+0 mask+0.076: 1(0,0) 2(-2.5,0)
  rect 1.1x8.2 smd paste+0 mask+0.076: 3(1.97,-4.93) 4(-5.07,-4.93)
  silkscreen extent -5.92,-9.03 4.6,0.95, body extent 0,0 0.25,0.25, height 0.25
CON_5013310807 [mm]
  rect 0.6x1.55 smd paste+0 mask+0.076: 1(0,0) 2(-1,0) 3(-2,0) 4(-3,0) 5(-4,0) 6(-5,0) 7(-6,0) 8(-7,0)
  rect 1.2x1.8 smd paste+0 mask+0.076: 9(1.3,-2.525) 10(-8.3,-2.525)
  silkscreen extent -8.62,-4.93 3.4,0.64, body extent 0,0 0.25,0.25, height 0.25
"D-SUB High Density 15 Position Male Conn-Footprint-1" [mil]
  rect 60x60 hole 30: 1(-170,100)
  round 60 hole 30: 2(-80,100) 3(10,100) 4(100,100) 5(190,100) 6(-215,0) 7(-125,0) 8(-35,0) 9(55,0) 10(145,0) 11(-170,-100) 12(-80,-100) 13(10,-100) 14(100,-100) 15(190,-100)
  round 177.17 hole 125.98: 16(-492.13,0) 17(492.13,0)
  silkscreen extent -610,-445 610,154
FP-0402-L_1_0_1-W_0_5_0_1-MFG [mm]
  rect 0.6x0.5 smd paste+0 mask+0: 1(-0.55,0) 2(0.55,0)
  silkscreen extent -0.55,-0.7 0.55,0.7, body extent -0.95,-0.4 0.95,0.4, height 0.25
FP-742C083-MFG [mm]
  rect 0.45x0.9 smd paste+0 mask+0: 1(-1.2,-0.85) 2(-0.4,-0.85) 3(0.4,-0.85) 4(1.2,-0.85) 5(1.2,0.85) 6(0.4,0.85) 7(-0.4,0.85) 8(-1.2,0.85)
  silkscreen extent -1.67,-2.05 1.67,0.03, body extent -1.6,-0.8 1.6,0.8, height 0.7
FP-501190-2017-MFG [mm]
  rect 0.6x1.6 smd paste+0 mask+0: 1(-4.5,-2.8) 2(-4.5,2.8) 3(-3.5,-2.8) 4(-3.5,2.8) 5(-2.5,-2.8) 6(-2.5,2.8) 7(-1.5,-2.8) 8(-1.5,2.8) 9(-0.5,-2.8) 10(-0.5,2.8) 11(0.5,-2.8) 12(0.5,2.8) 13(1.5,-2.8) 14(1.5,2.8) 15(2.5,-2.8) 16(2.5,2.8) 17(3.5,-2.8) 18(3.5,2.8) 19(4.5,-2.8) 20(4.5,2.8)
  rect 0.85x1.8 smd paste+0 mask+0: 21(-5.825,0.4) 22(5.825,0.4)
  silkscreen extent -6.25,-4.9 6.25,3.24, body extent -6.35,-4.37 6.35,3.7, height 0.25
FP-5055670271-MFG [mm]
  rect 0.8x1.2 smd paste+0 mask+0: 1(0.625,-1.9) 2(-0.625,-1.9)
  rect 1.3x2.15 smd paste+0 mask+0: 3(-2.525,0.395) 4(2.525,0.395)
  Keep-Out Layer region: 0.475,2.77 2.675,2.77 2.675,1.47 1.875,1.47 1.875,-0.68 3.475,-0.68 3.475,-2.7 1.025,-2.7 1.025,-1.3 0.475,-1.3 0.475,2.77
  Keep-Out Layer region: -0.475,2.77 -2.675,2.77 -2.675,1.47 -1.875,1.47 -1.875,-0.68 -3.475,-0.68 -3.475,-2.7 -1.025,-2.7 -1.025,-1.3 -0.475,-1.3 -0.475,2.77
  silkscreen extent -2.98,-3.2 2.98,2.05, body extent -3.47,-2.7 3.47,2.77, height 0.25
FP-C0402-BB-MFG [mm]
  rect 0.52x0.52 smd paste+0 mask+0: 1(-0.4,0) 2(0.4,0)
  silkscreen extent -0.5,-0.64 0.5,0.64, body extent -0.5,-0.25 0.5,0.25, height 0.55
FP-C0402C105K8PACTU-MFG [mm]
  rect 0.52x0.52 smd paste+0 mask+0: 1(-0.4,0) 2(0.4,0)
  silkscreen extent -0.67,-0.64 0.67,0.64, body extent -0.8,-0.4 0.8,0.4, height 0.25
FP-C2012-125-0_2-IPC_C [mm]
  rect 1.178x1.356 smd paste+0 mask+0: 1(-0.664,0) 2(0.664,0)
  silkscreen extent -1.25,-1.12 1.25,1.12, body extent -1.35,-0.82 1.35,0.82, height 0.25
FP-C3216-160-0_3-MFG [mm]
  rect 1.1x1.35 smd paste+0 mask+0: 1(-1.65,0) 2(1.65,0)
  silkscreen extent -0.72,-0.95 0.72,0.95, body extent -2.3,-1.05 2.3,1.05, height 0.25
FP-CL05A106MP5NUNC-MFG [mm]
  rect 0.45x0.675 smd paste+0 mask+0: 1(-0.463,0) 2(0.463,0)
  silkscreen extent -0.6,-0.62 0.6,0.62, body extent -0.79,-0.45 0.79,0.45, height 0.25
FP-GRM15-MFG [mm]
  rect 0.4x0.5 smd paste+0 mask+0: 1(-0.4,0) 2(0.4,0)
  silkscreen extent -0.53,-0.62 0.53,0.62, body extent -0.7,-0.38 0.7,0.38, height 0.25
FP-GRM155-0_1-IPC_B [mm]
  rect 0.615x0.572 smd paste+0 mask+0: 1(-0.429,0) 2(0.429,0)
  silkscreen extent -0.74,-0.69 0.74,0.69, body extent -0.89,-0.44 0.89,0.44, height 0.25
FP-SEAM-40-03_0-S-06-2-A-MFG [mm]
  round 0.64 smd paste-1000 mask-1000: A1(24.32,3.175) A2(23.05,3.175) A3(21.78,3.175) A4(20.51,3.175) A5(19.24,3.175) A6(17.97,3.175) A7(16.7,3.175) A8(15.43,3.175) A9(14.16,3.175) A10(12.89,3.175) A11(11.62,3.175) A12(10.35,3.175) A13(9.08,3.175) A14(7.81,3.175) A15(6.54,3.175) A16(5.27,3.175) A17(4,3.175) A18(2.73,3.175) A19(1.46,3.175) A20(0.19,3.175) A21(-1.08,3.175) A22(-2.35,3.175) A23(-3.62,3.175) A24(-4.89,3.175) A25(-6.16,3.175) A26(-7.43,3.175) A27(-8.7,3.175) A28(-9.97,3.175) A29(-11.24,3.175) A30(-12.51,3.175) A31(-13.78,3.175) A32(-15.05,3.175) A33(-16.32,3.175) A34(-17.59,3.175) A35(-18.86,3.175) A36(-20.13,3.175) A37(-21.4,3.175) A38(-22.67,3.175) A39(-23.94,3.175) A40(-25.21,3.175) B1(24.32,1.905) B2(23.05,1.905) B3(21.78,1.905) B4(20.51,1.905) B5(19.24,1.905) B6(17.97,1.905) B7(16.7,1.905) B8(15.43,1.905) B9(14.16,1.905) B10(12.89,1.905) B11(11.62,1.905) B12(10.35,1.905) B13(9.08,1.905) B14(7.81,1.905) B15(6.54,1.905) B16(5.27,1.905) B17(4,1.905) B18(2.73,1.905) B19(1.46,1.905) B20(0.19,1.905) B21(-1.08,1.905) B22(-2.35,1.905) B23(-3.62,1.905) B24(-4.89,1.905) B25(-6.16,1.905) B26(-7.43,1.905) B27(-8.7,1.905) B28(-9.97,1.905) B29(-11.24,1.905) B30(-12.51,1.905) B31(-13.78,1.905) B32(-15.05,1.905) B33(-16.32,1.905) B34(-17.59,1.905) B35(-18.86,1.905) B36(-20.13,1.905) B37(-21.4,1.905) B38(-22.67,1.905) B39(-23.94,1.905) B40(-25.21,1.905) C1(24.32,0.635) C2(23.05,0.635) C3(21.78,0.635) C4(20.51,0.635) C5(19.24,0.635) C6(17.97,0.635) C7(16.7,0.635) C8(15.43,0.635) C9(14.16,0.635) C10(12.89,0.635) C11(11.62,0.635) C12(10.35,0.635) C13(9.08,0.635) C14(7.81,0.635) C15(6.54,0.635) C16(5.27,0.635) C17(4,0.635) C18(2.73,0.635) C19(1.46,0.635) C20(0.19,0.635) C21(-1.08,0.635) C22(-2.35,0.635) C23(-3.62,0.635) C24(-4.89,0.635) C25(-6.16,0.635) C26(-7.43,0.635) C27(-8.7,0.635) C28(-9.97,0.635) C29(-11.24,0.635) C30(-12.51,0.635) C31(-13.78,0.635) C32(-15.05,0.635) C33(-16.32,0.635) C34(-17.59,0.635) C35(-18.86,0.635) C36(-20.13,0.635) C37(-21.4,0.635) C38(-22.67,0.635) C39(-23.94,0.635) C40(-25.21,0.635) D1(24.32,-0.635) D2(23.05,-0.635) D3(21.78,-0.635) D4(20.51,-0.635) D5(19.24,-0.635) D6(17.97,-0.635) D7(16.7,-0.635) D8(15.43,-0.635) D9(14.16,-0.635) D10(12.89,-0.635) D11(11.62,-0.635) D12(10.35,-0.635) D13(9.08,-0.635) D14(7.81,-0.635) D15(6.54,-0.635) D16(5.27,-0.635) D17(4,-0.635) D18(2.73,-0.635) D19(1.46,-0.635) D20(0.19,-0.635) D21(-1.08,-0.635) D22(-2.35,-0.635) D23(-3.62,-0.635) D24(-4.89,-0.635) D25(-6.16,-0.635) D26(-7.43,-0.635) D27(-8.7,-0.635) D28(-9.97,-0.635) D29(-11.24,-0.635) D30(-12.51,-0.635) D31(-13.78,-0.635) D32(-15.05,-0.635) D33(-16.32,-0.635) D34(-17.59,-0.635) D35(-18.86,-0.635) D36(-20.13,-0.635) D37(-21.4,-0.635) D38(-22.67,-0.635) D39(-23.94,-0.635) D40(-25.21,-0.635) E1(24.32,-1.905) E2(23.05,-1.905) E3(21.78,-1.905) E4(20.51,-1.905) E5(19.24,-1.905) E6(17.97,-1.905) E7(16.7,-1.905) E8(15.43,-1.905) E9(14.16,-1.905) E10(12.89,-1.905) E11(11.62,-1.905) E12(10.35,-1.905) E13(9.08,-1.905) E14(7.81,-1.905) E15(6.54,-1.905) E16(5.27,-1.905) E17(4,-1.905) E18(2.73,-1.905) E19(1.46,-1.905) E20(0.19,-1.905) E21(-1.08,-1.905) E22(-2.35,-1.905) E23(-3.62,-1.905) E24(-4.89,-1.905) E25(-6.16,-1.905) E26(-7.43,-1.905) E27(-8.7,-1.905) E28(-9.97,-1.905) E29(-11.24,-1.905) E30(-12.51,-1.905) E31(-13.78,-1.905) E32(-15.05,-1.905) E33(-16.32,-1.905) E34(-17.59,-1.905) E35(-18.86,-1.905) E36(-20.13,-1.905) E37(-21.4,-1.905) E38(-22.67,-1.905) E39(-23.94,-1.905) E40(-25.21,-1.905) F1(24.32,-3.175) F2(23.05,-3.175) F3(21.78,-3.175) F4(20.51,-3.175) F5(19.24,-3.175) F6(17.97,-3.175) F7(16.7,-3.175) F8(15.43,-3.175) F9(14.16,-3.175) F10(12.89,-3.175) F11(11.62,-3.175) F12(10.35,-3.175) F13(9.08,-3.175) F14(7.81,-3.175) F15(6.54,-3.175) F16(5.27,-3.175) F17(4,-3.175) F18(2.73,-3.175) F19(1.46,-3.175) F20(0.19,-3.175) F21(-1.08,-3.175) F22(-2.35,-3.175) F23(-3.62,-3.175) F24(-4.89,-3.175) F25(-6.16,-3.175) F26(-7.43,-3.175) F27(-8.7,-3.175) F28(-9.97,-3.175) F29(-11.24,-3.175) F30(-12.51,-3.175) F31(-13.78,-3.175) F32(-15.05,-3.175) F33(-16.32,-3.175) F34(-17.59,-3.175) F35(-18.86,-3.175) F36(-20.13,-3.175) F37(-21.4,-3.175) F38(-22.67,-3.175) F39(-23.94,-3.175) F40(-25.21,-3.175)
  round 1.27 hole 1.27 unplated paste-1000 mask+0: ""(-27.635,-3.05) ""(26.745,0)
  silkscreen extent -28.47,-4.87 29.37,4.87, body extent -28.34,-4.8 28.34,4.8, height 6.73
NDC0005A_M [mm] "SOT223, 5-Leads, Body 6.7x3.71mm, Pitch 1.5mm, IPC Low Density"
  rrect10% 2.2x1 smd: 1(-3.1,2.25) 2(-3.1,0.75) 3(-3.1,-0.75) 4(-3.1,-2.25)
  rrect5% 2.2x3.25 smd: 5(3.1,0)
  silkscreen extent -3.22,-3.35 1.7,3.42, body extent -3.48,-3.25 3.48,3.25, height 1.7
PicoClasp_Rcpt_10Pos_Vert [mm]
  rect 0.6x1.55 smd paste+0 mask+0.076: 1(0,0) 2(-1,0) 3(-2,0) 4(-3,0) 5(-4,0) 6(-5,0) 7(-6,0) 8(-7,0) 9(-8,0) 10(-9,0)
  rect 1.2x1.8 smd paste+0 mask+0.076: 11(1.3,-2.525) 12(-10.3,-2.525)
  silkscreen extent -10.62,-4.92 3.4,0.64, body extent -10.57,-5.27 1.68,0.25, height 5.62
PW0016A_L [mm] "SOP, 16-Leads, Body 5.1x4.5mm, Pitch 0.65mm, IPC High Density"
  rrect25% 1.2x0.4 smd: 1(-2.85,2.275) 2(-2.85,1.625) 3(-2.85,0.975) 4(-2.85,0.325) 5(-2.85,-0.325) 6(-2.85,-0.975) 7(-2.85,-1.625) 8(-2.85,-2.275) 9(2.85,-2.275) 10(2.85,-1.625) 11(2.85,-0.975) 12(2.85,-0.325) 13(2.85,0.325) 14(2.85,0.975) 15(2.85,1.625) 16(2.85,2.275)
  silkscreen extent -2.97,-2.55 1.85,3.15, body extent -3.21,-2.5 3.21,2.5, height 1
RESC0402(1005)_L [mm] "Chip Resistor, Body 1.0x0.5mm, IPC High Density"
  rrect25% 0.5x0.55 smd: 1(-0.45,0) 2(0.45,0)
  silkscreen extent 0,-0.2 0,0.2, body extent -0.5,-0.25 0.5,0.25, height 0.3
"WE-LHMI 4020"#1 [mm] "SMD Inductor, 2-Leads, Body 4.45 x 4.06mm"
  rect 1.5x2.4 smd: 1(-1.926,0) 2(1.926,0)
  Keep-Out Layer lines w0.127: -1,-2 -1,2 1,2 1,-2 -1,-2
  silkscreen extent -2.97,-2.2 2.2,2.2, body extent -2.22,-2.03 2.23,2.03, height 1.8
"WE-LHMI 4020"#2 [mm] "SMD Inductor, 2-Leads, Body 4.45 x 4.06mm"
  rect 1.5x2.4 smd: 1(-1.85,0) 2(1.85,0)
  Keep-Out Layer lines w0.127: -1,2 -1,-2 1,-2 1,2 -1,2
  silkscreen extent -2.97,-2.2 2.2,2.2, body extent -2.22,-2.03 2.23,2.03, height 1.8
